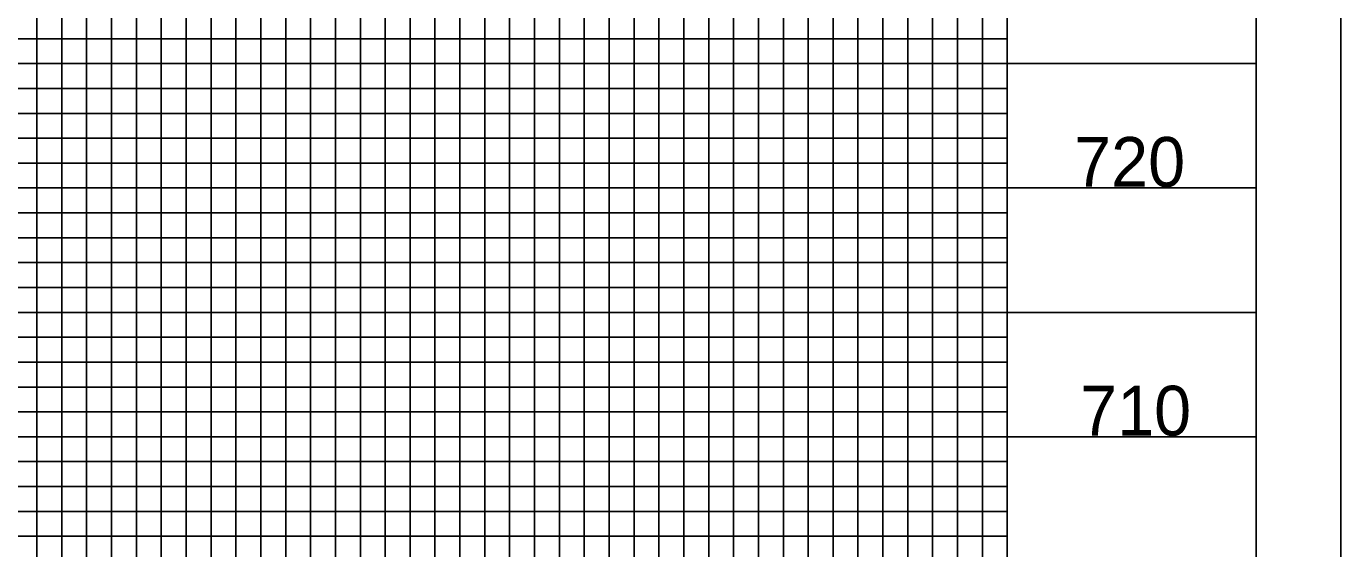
# Model space of a CAD drawing. Extents: x 1524869 to 1526553, y 501099 to 502199.
# Drawn here: x 1526289 to 1526553.1, y 501276.1 to 501381.1 of the extents above; entities that cross this region are included whole.
import ezdxf

# ---------------------------------------------------------------- set-up
doc = ezdxf.new("R2010")
doc.units = 0
for name, color, linetype in [('Exist Vertical Profile Vertical Axis Label', 7, 'Continuous'), ('Sheet Layout Profile Border Port 2', 7, 'Continuous'), ('Sheet Plot Border Outside CELL', 7, 'Continuous'), ('Sheet Profile CELL', 7, 'Continuous'), ('Sheet Profile Grid Major CELL', 7, 'Continuous'), ('Sheet Profile Grid Middle CELL', 7, 'Continuous'), ('Sheet Profile Grid Minor CELL', 7, 'Continuous')]:
    doc.layers.add(name, color=color, linetype=linetype)

msp = doc.modelspace()

# ---------------------------------------------------------------- linework, layer by layer
at = {"layer": 'Sheet Layout Profile Border Port 2'}
msp.add_lwpolyline([(1525086.08, 501648.56), (1526486.08, 501648.56), (1526486.08, 501148.56), (1525086.08, 501148.56)], close=True, dxfattribs=at)
at = {"layer": 'Sheet Plot Border Outside CELL'}
msp.add_lwpolyline([(1524869.08, 501098.56), (1526553.08, 501098.56), (1526553.08, 502198.56), (1524869.08, 502198.56)], close=True, dxfattribs=at)
at = {"layer": 'Sheet Profile CELL'}
msp.add_lwpolyline([(1526536.08, 502173.56), (1525036.08, 502173.56), (1525036.08, 501123.56), (1526536.08, 501123.56)], close=True, dxfattribs=at)
at = {"layer": 'Sheet Profile Grid Major CELL'}
for points in [[(1526086.08, 501148.56), (1526136.08, 501148.56), (1526136.08, 501648.56), (1526186.08, 501648.56), (1526186.08, 501148.56), (1526236.08, 501148.56), (1526236.08, 501648.56), (1526286.08, 501648.56), (1526286.08, 501148.56), (1526336.08, 501148.56), (1526336.08, 501648.56), (1526386.08, 501648.56), (1526386.08, 501148.56), (1526436.08, 501148.56), (1526436.08, 501148.56), (1526436.08, 501648.56), (1526486.08, 501648.56), (1526486.08, 501148.56)], [(1526536.08, 501348.56), (1525036.08, 501348.56), (1525036.08, 501298.56), (1526536.08, 501298.56)]]:
    msp.add_lwpolyline(points, dxfattribs=at)
at = {"layer": 'Sheet Profile Grid Middle CELL'}
for points in [[(1526111.08, 501148.56), (1526161.08, 501148.56), (1526161.08, 501648.56), (1526211.08, 501648.56), (1526211.08, 501148.56), (1526261.08, 501148.56), (1526261.08, 501648.56), (1526311.08, 501648.56), (1526311.08, 501148.56), (1526361.08, 501148.56), (1526361.08, 501648.56), (1526411.08, 501648.56), (1526411.08, 501148.56), (1526461.08, 501148.56), (1526461.08, 501648.56)], [(1526536.08, 501373.56), (1525036.08, 501373.56), (1525036.08, 501323.56), (1526536.08, 501323.56)]]:
    msp.add_lwpolyline(points, dxfattribs=at)
at = {"layer": 'Sheet Profile Grid Minor CELL'}
for p, q in [((1526486.08, 501378.56), (1525086.08, 501378.56)), ((1525086.08, 501368.56), (1526486.08, 501368.56)), ((1526486.08, 501363.56), (1525086.08, 501363.56)), ((1525086.08, 501358.56), (1526486.08, 501358.56)), ((1526486.08, 501353.56), (1525086.08, 501353.56)), ((1525086.08, 501343.56), (1526486.08, 501343.56)), ((1526486.08, 501338.56), (1525086.08, 501338.56)), ((1525086.08, 501333.56), (1526486.08, 501333.56)), ((1526486.08, 501328.56), (1525086.08, 501328.56)), ((1525086.08, 501318.56), (1526486.08, 501318.56)), ((1526486.08, 501313.56), (1525086.08, 501313.56)), ((1525086.08, 501308.56), (1526486.08, 501308.56)), ((1526486.08, 501303.56), (1525086.08, 501303.56)), ((1525086.08, 501293.56), (1526486.08, 501293.56)), ((1526486.08, 501288.56), (1525086.08, 501288.56)), ((1525086.08, 501283.56), (1526486.08, 501283.56)), ((1526486.08, 501278.56), (1525086.08, 501278.56))]:
    msp.add_line(p, q, dxfattribs=at)
for points in [[(1526291.08, 501648.56), (1526291.08, 501148.56), (1526296.08, 501148.56), (1526296.08, 501648.56)], [(1526301.08, 501648.56), (1526301.08, 501148.56), (1526306.08, 501148.56), (1526306.08, 501648.56)], [(1526316.08, 501648.56), (1526316.08, 501148.56), (1526321.08, 501148.56), (1526321.08, 501648.56)], [(1526326.08, 501648.56), (1526326.08, 501148.56), (1526331.08, 501148.56), (1526331.08, 501648.56)], [(1526341.08, 501648.56), (1526341.08, 501148.56), (1526346.08, 501148.56), (1526346.08, 501648.56)], [(1526351.08, 501648.56), (1526351.08, 501148.56), (1526356.08, 501148.56), (1526356.08, 501648.56)], [(1526366.08, 501648.56), (1526366.08, 501148.56), (1526371.08, 501148.56), (1526371.08, 501648.56)], [(1526376.08, 501648.56), (1526376.08, 501148.56), (1526381.08, 501148.56), (1526381.08, 501648.56)], [(1526391.08, 501648.56), (1526391.08, 501148.56), (1526396.08, 501148.56), (1526396.08, 501648.56)], [(1526401.08, 501648.56), (1526401.08, 501148.56), (1526406.08, 501148.56), (1526406.08, 501648.56)], [(1526416.08, 501648.56), (1526416.08, 501148.56), (1526421.08, 501148.56), (1526421.08, 501648.56)], [(1526426.08, 501648.56), (1526426.08, 501148.56), (1526431.08, 501148.56), (1526431.08, 501648.56)], [(1526441.08, 501648.56), (1526441.08, 501148.56), (1526446.08, 501148.56), (1526446.08, 501648.56)], [(1526451.08, 501648.56), (1526451.08, 501148.56), (1526456.08, 501148.56), (1526456.08, 501648.56)], [(1526466.08, 501648.56), (1526466.08, 501148.56), (1526471.08, 501148.56), (1526471.08, 501648.56)], [(1526476.08, 501648.56), (1526476.08, 501148.56), (1526481.08, 501148.56), (1526481.08, 501648.56)]]:
    msp.add_lwpolyline(points, dxfattribs=at)

# ---------------------------------------------------------------- texts
at = {"layer": 'Exist Vertical Profile Vertical Axis Label'}
for s, p in [('720', (1526499.51, 501348.81)), ('710', (1526500.71, 501298.81))]:
    msp.add_text(s, height=10, dxfattribs=at).set_placement(p)

doc.saveas('drawing.dxf')
